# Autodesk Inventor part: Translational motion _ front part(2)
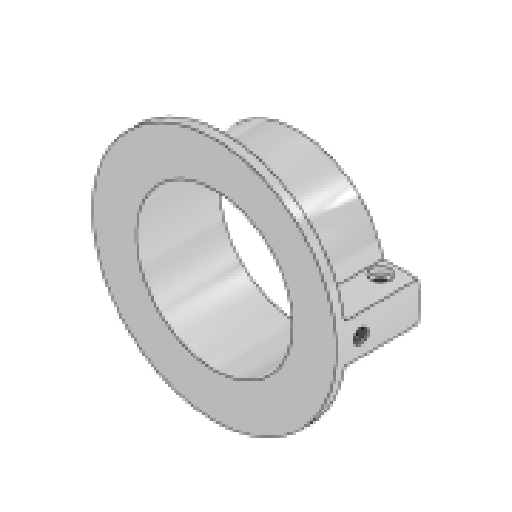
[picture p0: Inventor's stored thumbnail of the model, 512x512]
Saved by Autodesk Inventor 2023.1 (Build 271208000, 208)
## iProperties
Created: 2020-01
Part Number: Translational motion _ front part(2)
Material: Aluminum 6061
Document SubType Name: Modeling
Designer: ftrauzettel
Density: 2.7 g/cm^3
Appearance: Aluminum - Polished
Sending System: SolidWorks 2016
Last Author: Pam
Last Saved: 2020-10-15
Author: ftrauzettel
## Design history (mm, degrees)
mirror "Mirror1"
body "Solid1"
